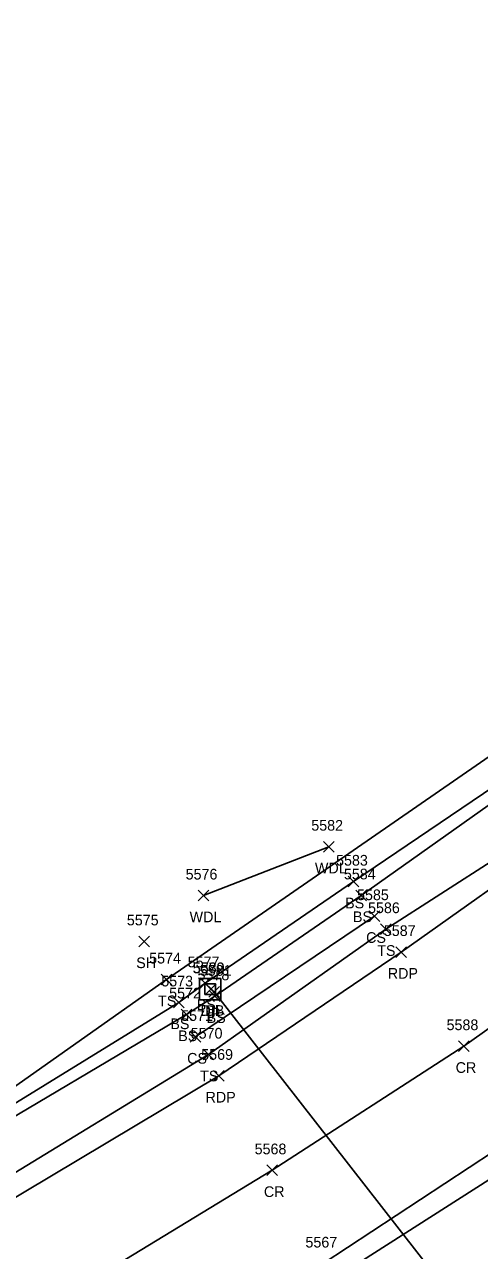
# Model space of a CAD drawing. Extents: x 1611797 to 1633212, y 298978 to 305475.
# Drawn here: x 1622176.9 to 1622262.1, y 300976.2 to 301205.8 of the extents above; entities that cross this region are included whole.
import ezdxf

# ---------------------------------------------------------------- set-up
doc = ezdxf.new("R2010")
doc.units = 0
for name, color, linetype in [('D_A', 7, 'Continuous'), ('D_I', 7, 'Continuous'), ('D_TIC', 7, 'Continuous'), ('DCP', 7, 'Continuous'), ('DS', 7, 'Continuous'), ('L_A', 7, 'Continuous'), ('L_I', 7, 'Continuous'), ('L_TIC', 7, 'Continuous'), ('LAWA', 7, 'Continuous'), ('LELB', 7, 'Continuous'), ('P_A', 7, 'Continuous'), ('P_I', 7, 'Continuous'), ('P_TIC', 7, 'Continuous'), ('PET', 7, 'Continuous'), ('PRC', 7, 'Continuous')]:
    doc.layers.add(name, color=color, linetype=linetype)

msp = doc.modelspace()

# ---------------------------------------------------------------- linework, layer by layer
at = {"layer": 'D_TIC'}
for points in [[(1622210.76, 301024.16), (1622212.76, 301026.16)], [(1622212.76, 301024.16), (1622210.76, 301026.16)], [(1622211.41, 301023.66), (1622213.41, 301025.66)], [(1622213.41, 301023.66), (1622211.41, 301025.66)]]:
    msp.add_lwpolyline(points, dxfattribs=at)
at = {"layer": 'DCP'}
msp.add_lwpolyline([(1622212.41, 301024.66), (1622282.17, 300935.22)], dxfattribs=at)
at = {"layer": 'DS'}
for p, q in [((1622209.65, 301027.13), (1622213.65, 301027.13)), ((1622209.65, 301023.13), (1622209.65, 301027.13)), ((1622210.65, 301024.13), (1622210.65, 301026.13)), ((1622210.65, 301026.13), (1622212.65, 301026.13)), ((1622212.65, 301026.13), (1622212.65, 301024.13)), ((1622213.65, 301027.13), (1622213.65, 301023.13)), ((1622212.65, 301024.13), (1622210.65, 301024.13)), ((1622211.66, 301025.13), (1622211.66, 301025.13)), ((1622211.66, 301025.13), (1622211.66, 301025.13)), ((1622213.65, 301023.13), (1622209.65, 301023.13))]:
    msp.add_line(p, q, dxfattribs=at)
at = {"layer": 'L_TIC'}
for points in [[(1622232.86, 301050.83), (1622234.86, 301052.83)], [(1622234.86, 301050.83), (1622232.86, 301052.83)], [(1622237.5, 301044.29), (1622239.5, 301046.29)], [(1622239.5, 301044.29), (1622237.5, 301046.29)], [(1622209.39, 301041.68), (1622211.39, 301043.68)], [(1622211.39, 301041.68), (1622209.39, 301043.68)], [(1622238.97, 301041.71), (1622240.97, 301043.71)], [(1622240.97, 301041.71), (1622238.97, 301043.71)], [(1622241.43, 301037.82), (1622243.43, 301039.82)], [(1622243.43, 301037.82), (1622241.43, 301039.82)], [(1622243.54, 301035.39), (1622245.54, 301037.39)], [(1622245.54, 301035.39), (1622243.54, 301037.39)], [(1622198.32, 301033.1), (1622200.32, 301035.1)], [(1622200.32, 301033.1), (1622198.32, 301035.1)], [(1622202.5, 301025.96), (1622204.5, 301027.96)], [(1622204.5, 301025.96), (1622202.5, 301027.96)], [(1622209.71, 301025.25), (1622211.71, 301027.25)], [(1622211.71, 301025.25), (1622209.71, 301027.25)], [(1622211.56, 301022.83), (1622213.56, 301024.83)], [(1622213.56, 301022.83), (1622211.56, 301024.83)], [(1622204.77, 301021.67), (1622206.77, 301023.67)], [(1622206.77, 301021.67), (1622204.77, 301023.67)], [(1622206.23, 301019.42), (1622208.23, 301021.42)], [(1622208.23, 301019.42), (1622206.23, 301021.42)], [(1622207.91, 301015.21), (1622209.91, 301017.21)], [(1622209.91, 301015.21), (1622207.91, 301017.21)], [(1622210.37, 301011.9), (1622212.37, 301013.9)], [(1622212.37, 301011.9), (1622210.37, 301013.9)]]:
    msp.add_lwpolyline(points, dxfattribs=at)
at = {"layer": 'LAWA'}
msp.add_lwpolyline([(1622210.39, 301042.68), (1622233.86, 301051.83)], dxfattribs=at)
at = {"layer": 'LELB'}
for points in [[(1622141.83, 300898.34), (1622139.55, 300912.95), (1622151.09, 300921.4), (1622196.53, 300946.85), (1622234.34, 300970.61), (1622271.97, 300994.63), (1622303.88, 301017.35), (1622337.87, 301043.51), (1622376.19, 301076.15), (1622406.41, 301102.71), (1622438.28, 301133.32), (1622472.59, 301167.8), (1622503.26, 301203.44), (1622524.06, 301228.28), (1622546.3, 301255.74), (1622570.57, 301288.87), (1622594.14, 301322.09), (1622614.94, 301354.98), (1622632.15, 301381.37), (1622641.11, 301374.53), (1622644.03, 301365.27)], [(1622140.33, 300985.53), (1622162.65, 300998.17), (1622203.5, 301026.96), (1622265.71, 301069.94), (1622286.44, 301082.83), (1622289.5, 301084.51), (1622293.5, 301079.88), (1622293.54, 301073.26)], [(1622132.27, 300994.56), (1622140.33, 300985.53), (1622141.57, 300983.63), (1622143.17, 300982.53), (1622164.66, 300995.17), (1622207.23, 301020.42), (1622212.56, 301023.83), (1622239.97, 301042.71), (1622270.17, 301064.09), (1622287.87, 301078.29), (1622287.07, 301079.42)], [(1622141.57, 300983.63), (1622163.48, 300996.62), (1622205.77, 301022.67), (1622210.71, 301026.25), (1622238.5, 301045.29), (1622268.87, 301065.86), (1622287.07, 301079.42)], [(1622127.13, 300993.42), (1622136.36, 300983.99), (1622142.26, 300980.7), (1622150.11, 300977.37), (1622169.41, 300987.35), (1622211.37, 301012.9), (1622244.54, 301036.39), (1622275.48, 301056.25), (1622293.54, 301073.26)], [(1622208.91, 301016.21), (1622242.43, 301038.82)]]:
    msp.add_lwpolyline(points, dxfattribs=at)
at = {"layer": 'P_TIC'}
for points in [[(1622246.45, 301031.11), (1622248.45, 301033.11)], [(1622248.45, 301031.11), (1622246.45, 301033.11)], [(1622258.2, 301013.48), (1622260.2, 301015.48)], [(1622260.2, 301013.48), (1622258.2, 301015.48)], [(1622212.31, 301007.93), (1622214.31, 301009.93)], [(1622214.31, 301007.93), (1622212.31, 301009.93)], [(1622222.3, 300990.24), (1622224.3, 300992.24)], [(1622224.3, 300990.24), (1622222.3, 300992.24)]]:
    msp.add_lwpolyline(points, dxfattribs=at)
at = {"layer": 'PET'}
for points in [[(1622171.31, 300983.91), (1622213.31, 301008.93), (1622247.45, 301032.11), (1622277.72, 301053.56), (1622294.6, 301066.05), (1622297.06, 301070.19), (1622323.76, 301091.16), (1622328.52, 301093.64), (1622348.58, 301110.76), (1622377.82, 301136.98), (1622408.25, 301165.87), (1622439.39, 301198.04)], [(1621877.51, 300819.53), (1621921.58, 300831.86), (1621962.65, 300844.86), (1621990.49, 300854.45), (1622037.78, 300873.03), (1622075.03, 300888.63), (1622109.87, 300905.22), (1622116.63, 300908.47), (1622136.93, 300918.35), (1622148.95, 300924.98), (1622194.49, 300950.49), (1622232.81, 300973.78), (1622269.29, 300997.78), (1622300.77, 301020.41), (1622337.8, 301049.3), (1622373.72, 301078.69), (1622403.36, 301105.61), (1622435.21, 301136.14)]]:
    msp.add_lwpolyline(points, dxfattribs=at)
at = {"layer": 'PRC'}
msp.add_lwpolyline([(1621873.52, 300838.62), (1621915.14, 300850.35), (1621960.25, 300864.42), (1621990.56, 300875.62), (1622029.66, 300890.77), (1622067.46, 300906.99), (1622101.01, 300922.62), (1622138.29, 300941.67), (1622182.77, 300966.6), (1622223.3, 300991.24), (1622259.2, 301014.48), (1622289.46, 301035.95), (1622325.15, 301063.44), (1622360.89, 301093.19), (1622391.65, 301120.64), (1622424.38, 301151.76)], dxfattribs=at)

# ---------------------------------------------------------------- texts
at = {"layer": 'D_A'}
for s, p in [('DIB', (1622209.86, 301020.16)), ('DI', (1622210.71, 301020.13)), ('P', (1622211.79, 301019.66))]:
    msp.add_text(s, height=2, dxfattribs=at).set_placement(p)
at = {"layer": 'D_I'}
for s, p in [('5579', (1622208.39, 301028.13)), ('5580', (1622208.41, 301028.16)), ('5581', (1622209.72, 301027.66))]:
    msp.add_text(s, height=2, dxfattribs=at).set_placement(p)
at = {"layer": 'L_A'}
for s, p in [('WDL', (1622231.28, 301046.83)), ('BS', (1622236.94, 301040.29)), ('WDL', (1622207.81, 301037.68)), ('BS', (1622238.41, 301037.71)), ('CS', (1622240.87, 301033.82)), ('TS', (1622242.95, 301031.39)), ('SH', (1622197.81, 301029.1)), ('TS', (1622201.91, 301021.96)), ('BS', (1622209.15, 301021.25)), ('BS', (1622204.21, 301017.67)), ('BS', (1622211, 301018.83)), ('BS', (1622205.68, 301015.42)), ('CS', (1622207.35, 301011.21)), ('TS', (1622209.78, 301007.9))]:
    msp.add_text(s, height=2, dxfattribs=at).set_placement(p)
at = {"layer": 'L_I'}
for s, p in [('5582', (1622230.6, 301054.83)), ('5583', (1622235.24, 301048.29)), ('5576', (1622207.07, 301045.68)), ('5584', (1622236.71, 301045.71)), ('5585', (1622239.17, 301041.82)), ('5586', (1622241.23, 301039.39)), ('5575', (1622196.06, 301037.1)), ('5574', (1622200.24, 301029.96)), ('5577', (1622207.45, 301029.25)), ('5578', (1622209.3, 301026.83)), ('5573', (1622202.51, 301025.67)), ('5572', (1622203.98, 301023.42)), ('5571', (1622206.22, 301019.21)), ('5570', (1622208.02, 301015.9))]:
    msp.add_text(s, height=2, dxfattribs=at).set_placement(p)
at = {"layer": 'P_A'}
for s, p in [('RDP', (1622244.93, 301027.11)), ('CR', (1622257.64, 301009.48)), ('RDP', (1622210.8, 301003.93)), ('CR', (1622221.73, 300986.24))]:
    msp.add_text(s, height=2, dxfattribs=at).set_placement(p)
at = {"layer": 'P_I'}
for s, p in [('5587', (1622244.19, 301035.11)), ('5588', (1622255.94, 301017.48)), ('5569', (1622209.99, 301011.93)), ('5568', (1622219.99, 300994.24)), ('5567', (1622229.51, 300976.78))]:
    msp.add_text(s, height=2, dxfattribs=at).set_placement(p)

doc.saveas('drawing.dxf')
